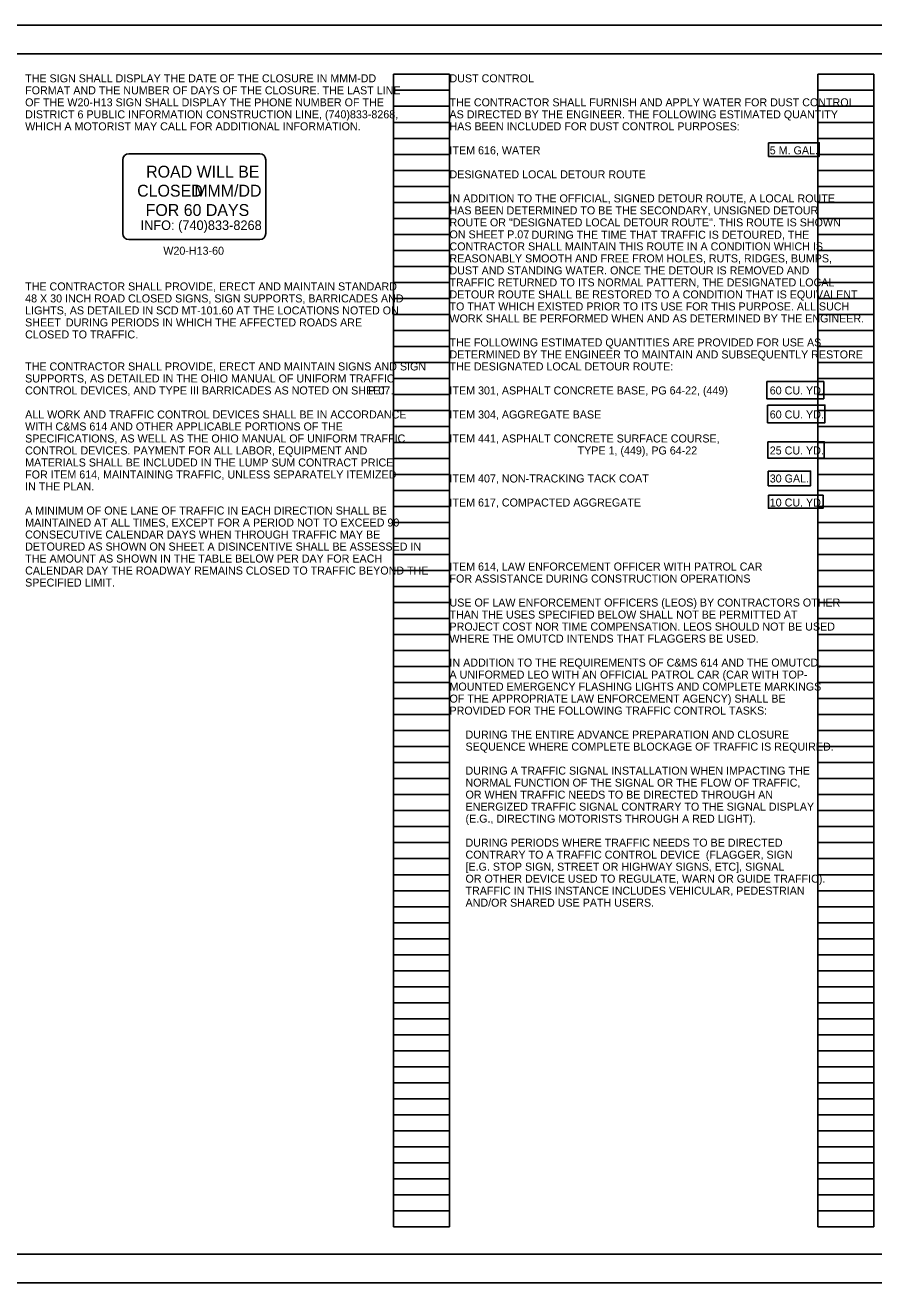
# Model space of a CAD drawing. Extents: x -14.4 to 34, y 0 to 22.
# Drawn here: x 9.82 to 24.66, y 0 to 22 of the extents above; entities that cross this region are included whole.
import ezdxf

# ---------------------------------------------------------------- set-up
doc = ezdxf.new("R2010")
doc.units = 0
for name, color, linetype in [('SH_Border', 7, 'Continuous'), ('SH_Cut_Line', 7, 'Continuous'), ('SH_Data', 7, 'Continuous'), ('SH_Text', 7, 'Continuous'), ('SN_X_Public', 7, 'Continuous')]:
    doc.layers.add(name, color=color, linetype=linetype)

msp = doc.modelspace()

# ---------------------------------------------------------------- linework, layer by layer
at = {"layer": 'SH_Border'}
for points in [[(22.819, 19.943), (23.707, 19.943), (23.707, 19.705), (22.819, 19.705)], [(22.787, 15.766), (23.785, 15.766), (23.785, 15.466), (22.787, 15.466)], [(22.803, 15.353), (23.806, 15.353), (23.806, 15.045), (22.803, 15.045)], [(22.809, 14.713), (23.794, 14.713), (23.794, 14.425), (22.809, 14.425)], [(22.813, 14.2), (23.554, 14.2), (23.554, 13.942), (22.813, 13.942)], [(22.816, 13.778), (23.774, 13.778), (23.774, 13.549), (22.816, 13.549)]]:
    msp.add_lwpolyline(points, close=True, dxfattribs=at)
at = {"layer": 'SH_Cut_Line'}
for p, q in [((16.26, 0.98), (16.26, 21.14)), ((16.26, 21.14), (17.24, 21.14)), ((17.24, 0.98), (17.24, 21.14)), ((23.68, 0.98), (23.68, 21.14)), ((23.68, 21.14), (24.66, 21.14)), ((24.66, 0.98), (24.66, 21.14)), ((16.26, 20.86), (17.24, 20.86)), ((23.68, 20.86), (24.66, 20.86)), ((16.26, 20.58), (17.24, 20.58)), ((23.68, 20.58), (24.66, 20.58)), ((16.26, 20.3), (17.24, 20.3)), ((23.68, 20.3), (24.66, 20.3)), ((16.26, 20.02), (17.24, 20.02)), ((23.68, 20.02), (24.66, 20.02)), ((16.26, 19.74), (17.24, 19.74)), ((23.68, 19.74), (24.66, 19.74)), ((16.26, 19.46), (17.24, 19.46)), ((23.68, 19.46), (24.66, 19.46)), ((16.26, 19.18), (17.24, 19.18)), ((23.68, 19.18), (24.66, 19.18)), ((16.26, 18.9), (17.24, 18.9)), ((23.68, 18.9), (24.66, 18.9)), ((16.26, 18.62), (17.24, 18.62)), ((23.68, 18.62), (24.66, 18.62)), ((16.26, 18.34), (17.24, 18.34)), ((23.68, 18.34), (24.66, 18.34)), ((16.26, 18.06), (17.24, 18.06)), ((23.68, 18.06), (24.66, 18.06)), ((16.26, 17.78), (17.24, 17.78)), ((23.68, 17.78), (24.66, 17.78)), ((16.26, 17.5), (17.24, 17.5)), ((23.68, 17.5), (24.66, 17.5)), ((16.26, 17.22), (17.24, 17.22)), ((23.68, 17.22), (24.66, 17.22)), ((16.26, 16.94), (17.24, 16.94)), ((23.68, 16.94), (24.66, 16.94)), ((16.26, 16.66), (17.24, 16.66)), ((23.68, 16.66), (24.66, 16.66)), ((16.26, 16.38), (17.24, 16.38)), ((23.68, 16.38), (24.66, 16.38)), ((16.26, 16.1), (17.24, 16.1)), ((23.68, 16.1), (24.66, 16.1)), ((16.26, 15.82), (17.24, 15.82)), ((23.68, 15.82), (24.66, 15.82)), ((16.26, 15.54), (17.24, 15.54)), ((23.68, 15.54), (24.66, 15.54)), ((16.26, 15.26), (17.24, 15.26)), ((23.68, 15.26), (24.66, 15.26)), ((16.26, 14.98), (17.24, 14.98)), ((23.68, 14.98), (24.66, 14.98)), ((16.26, 14.7), (17.24, 14.7)), ((23.68, 14.7), (24.66, 14.7)), ((16.26, 14.42), (17.24, 14.42)), ((23.68, 14.42), (24.66, 14.42)), ((16.26, 14.14), (17.24, 14.14)), ((23.68, 14.14), (24.66, 14.14)), ((16.26, 13.86), (17.24, 13.86)), ((23.68, 13.86), (24.66, 13.86)), ((16.26, 13.58), (17.24, 13.58)), ((23.68, 13.58), (24.66, 13.58)), ((16.26, 13.3), (17.24, 13.3)), ((23.68, 13.3), (24.66, 13.3)), ((16.26, 13.02), (17.24, 13.02)), ((23.68, 13.02), (24.66, 13.02)), ((16.26, 12.74), (17.24, 12.74)), ((23.68, 12.74), (24.66, 12.74)), ((16.26, 12.46), (17.24, 12.46)), ((23.68, 12.46), (24.66, 12.46)), ((16.26, 12.18), (17.24, 12.18)), ((23.68, 12.18), (24.66, 12.18)), ((16.26, 11.9), (17.24, 11.9)), ((23.68, 11.9), (24.66, 11.9)), ((16.26, 11.62), (17.24, 11.62)), ((23.68, 11.62), (24.66, 11.62)), ((16.26, 11.34), (17.24, 11.34)), ((23.68, 11.34), (24.66, 11.34)), ((16.26, 11.06), (17.24, 11.06)), ((23.68, 11.06), (24.66, 11.06)), ((16.26, 10.78), (17.24, 10.78)), ((23.68, 10.78), (24.66, 10.78)), ((16.26, 10.5), (17.24, 10.5)), ((23.68, 10.5), (24.66, 10.5)), ((16.26, 10.22), (17.24, 10.22)), ((23.68, 10.22), (24.66, 10.22)), ((16.26, 9.94), (17.24, 9.94)), ((23.68, 9.94), (24.66, 9.94)), ((16.26, 9.66), (17.24, 9.66)), ((23.68, 9.66), (24.66, 9.66)), ((16.26, 9.38), (17.24, 9.38)), ((23.68, 9.38), (24.66, 9.38)), ((16.26, 9.1), (17.24, 9.1)), ((23.68, 9.1), (24.66, 9.1)), ((16.26, 8.82), (17.24, 8.82)), ((23.68, 8.82), (24.66, 8.82)), ((16.26, 8.54), (17.24, 8.54)), ((23.68, 8.54), (24.66, 8.54)), ((16.26, 8.26), (17.24, 8.26)), ((23.68, 8.26), (24.66, 8.26)), ((16.26, 7.98), (17.24, 7.98)), ((23.68, 7.98), (24.66, 7.98)), ((16.26, 7.7), (17.24, 7.7)), ((23.68, 7.7), (24.66, 7.7)), ((16.26, 7.42), (17.24, 7.42)), ((23.68, 7.42), (24.66, 7.42)), ((16.26, 7.14), (17.24, 7.14)), ((23.68, 7.14), (24.66, 7.14)), ((16.26, 6.86), (17.24, 6.86)), ((23.68, 6.86), (24.66, 6.86)), ((16.26, 6.58), (17.24, 6.58)), ((23.68, 6.58), (24.66, 6.58)), ((16.26, 6.3), (17.24, 6.3)), ((23.68, 6.3), (24.66, 6.3)), ((16.26, 6.02), (17.24, 6.02)), ((23.68, 6.02), (24.66, 6.02)), ((16.26, 5.74), (17.24, 5.74)), ((23.68, 5.74), (24.66, 5.74)), ((16.26, 5.46), (17.24, 5.46)), ((23.68, 5.46), (24.66, 5.46)), ((16.26, 5.18), (17.24, 5.18)), ((23.68, 5.18), (24.66, 5.18)), ((16.26, 4.9), (17.24, 4.9)), ((23.68, 4.9), (24.66, 4.9)), ((16.26, 4.62), (17.24, 4.62)), ((23.68, 4.62), (24.66, 4.62)), ((16.26, 4.34), (17.24, 4.34)), ((23.68, 4.34), (24.66, 4.34)), ((16.26, 4.06), (17.24, 4.06)), ((23.68, 4.06), (24.66, 4.06)), ((16.26, 3.78), (17.24, 3.78)), ((23.68, 3.78), (24.66, 3.78)), ((16.26, 3.5), (17.24, 3.5)), ((23.68, 3.5), (24.66, 3.5)), ((16.26, 3.22), (17.24, 3.22)), ((23.68, 3.22), (24.66, 3.22)), ((16.26, 2.94), (17.24, 2.94)), ((23.68, 2.94), (24.66, 2.94)), ((16.26, 2.66), (17.24, 2.66)), ((23.68, 2.66), (24.66, 2.66)), ((16.26, 2.38), (17.24, 2.38)), ((23.68, 2.38), (24.66, 2.38)), ((16.26, 2.1), (17.24, 2.1)), ((23.68, 2.1), (24.66, 2.1)), ((16.26, 1.82), (17.24, 1.82)), ((23.68, 1.82), (24.66, 1.82)), ((16.26, 1.54), (17.24, 1.54)), ((23.68, 1.54), (24.66, 1.54)), ((16.26, 1.26), (17.24, 1.26)), ((23.68, 1.26), (24.66, 1.26)), ((16.26, 0.98), (17.24, 0.98)), ((23.68, 0.98), (24.66, 0.98))]:
    msp.add_line(p, q, dxfattribs=at)
at = {"layer": 'SH_Data'}
msp.add_lwpolyline([(1.5, 21.5), (33.5, 21.5), (33.5, 0.5), (1.5, 0.5)], close=True, dxfattribs=at)
at = {"layer": 'SH_Text'}
msp.add_lwpolyline([(0, 0), (34, 0), (34, 22), (0, 22)], close=True, dxfattribs=at)
at = {"layer": 'SN_X_Public'}
for p, q in [((11.527, 19.646), (11.527, 18.354)), ((13.923, 19.75), (11.631, 19.75)), ((14.027, 18.354), (14.027, 19.646)), ((11.631, 18.25), (13.923, 18.25))]:
    msp.add_line(p, q, dxfattribs=at)
for centre, start, end in [((11.631, 19.646), 90, 180), ((13.923, 19.646), 0, 90), ((11.631, 18.354), 180, 270), ((13.923, 18.354), 270, 360)]:
    msp.add_arc(centre, 0.104, start, end, dxfattribs=at)

# ---------------------------------------------------------------- texts
at = {"layer": 'SH_Border'}
for s, p in [('THE SIGN SHALL DISPLAY THE DATE OF THE CLOSURE IN MMM-DD ', (9.82, 21)), ('DUST CONTROL', (17.24, 21)), ('FORMAT AND THE NUMBER OF DAYS OF THE CLOSURE. THE LAST LINE ', (9.82, 20.79)), ('OF THE W20-H13 SIGN SHALL DISPLAY THE PHONE NUMBER OF THE ', (9.82, 20.58)), ('THE CONTRACTOR SHALL FURNISH AND APPLY WATER FOR DUST CONTROL ', (17.24, 20.58)), ('DISTRICT 6 PUBLIC INFORMATION CONSTRUCTION LINE, (740)833-8268, ', (9.82, 20.37)), ('AS DIRECTED BY THE ENGINEER. THE FOLLOWING ESTIMATED QUANTITY ', (17.24, 20.37)), ('WHICH A MOTORIST MAY CALL FOR ADDITIONAL INFORMATION. ', (9.82, 20.16)), ('HAS BEEN INCLUDED FOR DUST CONTROL PURPOSES:', (17.24, 20.16)), ('ITEM 616, WATER', (17.24, 19.74)), ('5 M. GAL.', (22.84, 19.74)), ('DESIGNATED LOCAL DETOUR ROUTE', (17.24, 19.32)), ('IN ADDITION TO THE OFFICIAL, SIGNED DETOUR ROUTE, A LOCAL ROUTE ', (17.24, 18.9)), ('HAS BEEN DETERMINED TO BE THE SECONDARY, UNSIGNED DETOUR ', (17.24, 18.69)), ('ROUTE OR "DESIGNATED LOCAL DETOUR ROUTE". THIS ROUTE IS SHOWN ', (17.24, 18.48)), ('ON SHEET P.07', (17.24, 18.27)), ('. DURING THE TIME THAT TRAFFIC IS DETOURED, THE ', (18.57, 18.264)), ('W20-H13-60', (12.236, 17.984)), ('CONTRACTOR SHALL MAINTAIN THIS ROUTE IN A CONDITION WHICH IS ', (17.24, 18.06)), ('REASONABLY SMOOTH AND FREE FROM HOLES, RUTS, RIDGES, BUMPS, ', (17.24, 17.85)), ('DUST AND STANDING WATER. ONCE THE DETOUR IS REMOVED AND ', (17.24, 17.64)), ('THE CONTRACTOR SHALL PROVIDE, ERECT AND MAINTAIN STANDARD ', (9.82, 17.36)), ('TRAFFIC RETURNED TO ITS NORMAL PATTERN, THE DESIGNATED LOCAL ', (17.24, 17.43)), ('48 X 30 INCH ROAD CLOSED SIGNS, SIGN SUPPORTS, BARRICADES AND ', (9.82, 17.15)), ('DETOUR ROUTE SHALL BE RESTORED TO A CONDITION THAT IS EQUIVALENT ', (17.24, 17.22)), ('LIGHTS, AS DETAILED IN SCD MT-101.60 AT THE LOCATIONS NOTED ON ', (9.82, 16.94)), ('WORK SHALL BE PERFORMED WHEN AND AS DETERMINED BY THE ENGINEER.', (17.24, 16.8)), ('TO THAT WHICH EXISTED PRIOR TO ITS USE FOR THIS PURPOSE. ALL SUCH ', (17.24, 17.01)), ('SHEET ', (9.82, 16.73)), (' DURING PERIODS IN WHICH THE AFFECTED ROADS ARE ', (10.48, 16.73)), ('CLOSED TO TRAFFIC.', (9.82, 16.52)), ('THE FOLLOWING ESTIMATED QUANTITIES ARE PROVIDED FOR USE AS ', (17.24, 16.38)), ('DETERMINED BY THE ENGINEER TO MAINTAIN AND SUBSEQUENTLY RESTORE ', (17.24, 16.17)), ('THE CONTRACTOR SHALL PROVIDE, ERECT AND MAINTAIN SIGNS AND SIGN ', (9.82, 15.96)), ('THE DESIGNATED LOCAL DETOUR ROUTE:', (17.24, 15.96)), ('SUPPORTS, AS DETAILED IN THE OHIO MANUAL OF UNIFORM TRAFFIC ', (9.82, 15.75)), ('CONTROL DEVICES, AND TYPE III BARRICADES AS NOTED ON SHEET ', (9.82, 15.54)), ('P.07', (15.819, 15.54)), ('ITEM 301, ASPHALT CONCRETE BASE, PG 64-22, (449)', (17.24, 15.54)), ('60 CU. YD.', (22.84, 15.54)), ('.', (16.212, 15.54)), ('ALL WORK AND TRAFFIC CONTROL DEVICES SHALL BE IN ACCORDANCE ', (9.82, 15.12)), ('ITEM 304, AGGREGATE BASE', (17.24, 15.12)), ('60 CU. YD.', (22.84, 15.12)), ('WITH C&MS 614 AND OTHER APPLICABLE PORTIONS OF THE ', (9.82, 14.91)), ('SPECIFICATIONS, AS WELL AS THE OHIO MANUAL OF UNIFORM TRAFFIC ', (9.82, 14.7)), ('ITEM 441, ASPHALT CONCRETE SURFACE COURSE,', (17.24, 14.7)), ('CONTROL DEVICES. PAYMENT FOR ALL LABOR, EQUIPMENT AND ', (9.82, 14.49)), ('TYPE 1, (449), PG 64-22', (19.48, 14.49)), ('25 CU. YD.', (22.84, 14.49)), ('MATERIALS SHALL BE INCLUDED IN THE LUMP SUM CONTRACT PRICE ', (9.82, 14.28)), ('FOR ITEM 614, MAINTAINING TRAFFIC, UNLESS SEPARATELY ITEMIZED ', (9.82, 14.07)), ('ITEM 407, NON-TRACKING TACK COAT', (17.24, 14)), ('30 GAL.', (22.84, 14)), ('IN THE PLAN.', (9.82, 13.86)), ('ITEM 617, COMPACTED AGGREGATE', (17.24, 13.58)), ('10 CU. YD.', (22.84, 13.58)), ('A MINIMUM OF ONE LANE OF TRAFFIC IN EACH DIRECTION SHALL BE ', (9.82, 13.44)), ('MAINTAINED AT ALL TIMES, EXCEPT FOR A PERIOD NOT TO EXCEED 90 ', (9.82, 13.23)), ('CONSECUTIVE CALENDAR DAYS WHEN THROUGH TRAFFIC MAY BE ', (9.82, 13.02)), ('DETOURED AS SHOWN ON SHEET ', (9.82, 12.81)), ('. A DISINCENTIVE SHALL BE ASSESSED IN ', (12.905, 12.81)), ('THE AMOUNT AS SHOWN IN THE TABLE BELOW PER DAY FOR EACH ', (9.82, 12.6)), ('ITEM 614, LAW ENFORCEMENT OFFICER WITH PATROL CAR', (17.24, 12.46)), ('SPECIFIED LIMIT.', (9.82, 12.18)), ('CALENDAR DAY THE ROADWAY REMAINS CLOSED TO TRAFFIC BEYOND THE ', (9.82, 12.39)), ('FOR ASSISTANCE DURING CONSTRUCTION OPERATIONS', (17.24, 12.25)), ('USE OF LAW ENFORCEMENT OFFICERS (LEOS) BY CONTRACTORS OTHER ', (17.24, 11.83)), ('THAN THE USES SPECIFIED BELOW SHALL NOT BE PERMITTED AT ', (17.24, 11.62)), ('PROJECT COST NOR TIME COMPENSATION. LEOS SHOULD NOT BE USED ', (17.24, 11.41)), ('WHERE THE OMUTCD INTENDS THAT FLAGGERS BE USED.', (17.24, 11.2)), ('IN ADDITION TO THE REQUIREMENTS OF C&MS 614 AND THE OMUTCD, ', (17.24, 10.78)), ('A UNIFORMED LEO WITH AN OFFICIAL PATROL CAR (CAR WITH TOP-', (17.24, 10.57)), ('MOUNTED EMERGENCY FLASHING LIGHTS AND COMPLETE MARKINGS ', (17.24, 10.36)), ('OF THE APPROPRIATE LAW ENFORCEMENT AGENCY) SHALL BE ', (17.24, 10.15)), ('PROVIDED FOR THE FOLLOWING TRAFFIC CONTROL TASKS:', (17.24, 9.94)), ('DURING THE ENTIRE ADVANCE PREPARATION AND CLOSURE ', (17.52, 9.52)), ('SEQUENCE WHERE COMPLETE BLOCKAGE OF TRAFFIC IS REQUIRED.', (17.52, 9.31)), ('DURING A TRAFFIC SIGNAL INSTALLATION WHEN IMPACTING THE ', (17.52, 8.89)), ('NORMAL FUNCTION OF THE SIGNAL OR THE FLOW OF TRAFFIC, ', (17.52, 8.68)), ('OR WHEN TRAFFIC NEEDS TO BE DIRECTED THROUGH AN ', (17.52, 8.47)), ('ENERGIZED TRAFFIC SIGNAL CONTRARY TO THE SIGNAL DISPLAY ', (17.52, 8.26)), ('(E.G., DIRECTING MOTORISTS THROUGH A RED LIGHT).', (17.52, 8.05)), ('DURING PERIODS WHERE TRAFFIC NEEDS TO BE DIRECTED ', (17.52, 7.63)), ('CONTRARY TO A TRAFFIC CONTROL DEVICE  (FLAGGER, SIGN ', (17.52, 7.42)), ('[E.G. STOP SIGN, STREET OR HIGHWAY SIGNS, ETC], SIGNAL ', (17.52, 7.21)), ('OR OTHER DEVICE USED TO REGULATE, WARN OR GUIDE TRAFFIC). ', (17.52, 7)), ('TRAFFIC IN THIS INSTANCE INCLUDES VEHICULAR, PEDESTRIAN ', (17.52, 6.79)), ('AND/OR SHARED USE PATH USERS.', (17.52, 6.58))]:
    msp.add_text(s, height=0.14, dxfattribs=at).set_placement(p)
at = {"layer": 'SN_X_Public'}
for s, height, p in [('ROAD WILL BE', 0.20833, (11.936, 19.333)), ('CLOSED', 0.2083, (11.779, 19)), ('MMM/DD', 0.2083, (12.777, 19)), ('FOR 60 DAYS', 0.20833, (11.927, 18.662)), ('INFO: (740)833-8268', 0.16658, (11.839, 18.417))]:
    msp.add_text(s, height=height, dxfattribs=at).set_placement(p)

doc.saveas('drawing.dxf')
